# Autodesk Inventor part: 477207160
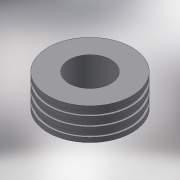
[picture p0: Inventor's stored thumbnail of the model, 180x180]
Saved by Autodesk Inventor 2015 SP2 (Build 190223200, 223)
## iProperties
Created: 2017-08
Part Number: 477207160
Material: Generic
Description: PLASSON MAN HOLE ADAPTOR 160
Document SubType Name: Modeling
Designer: Кирилл
Density: 1 g/cm^3
Appearance: Default
Author: Кирилл
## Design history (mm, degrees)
derived "37020-477207.ipt"
feature "Solid1::37020-477207.ipt"
tag "TaggingFeature1"
body "Solid1"
other parameters: "d0" = 135, "d2" = 266, "d3" = 141, "d6" = 39, "L_" = 135, "d_1" = 141, "H_" = 39
